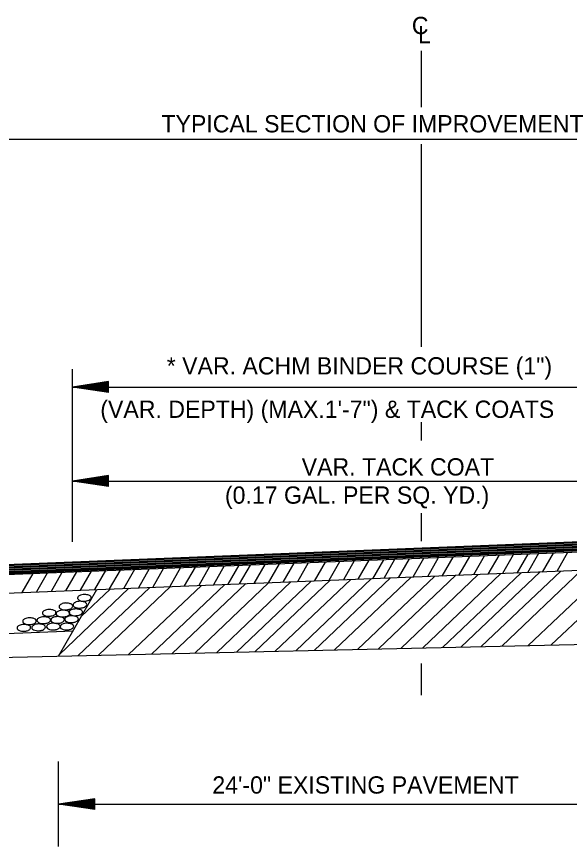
# Model space of a CAD drawing. Extents: x 634177 to 635904, y 289936 to 290970.
# Drawn here: x 635697.85 to 635717.06, y 290601.34 to 290630.14 of the extents above; entities that cross this region are included whole.
import ezdxf

# ---------------------------------------------------------------- set-up
doc = ezdxf.new("R2010")
doc.units = 0
doc.layers.add('R_Draft', color=7, linetype='Continuous')

msp = doc.modelspace()

# ---------------------------------------------------------------- linework, layer by layer
at = {"layer": 'R_Draft'}
for p, q in [((635711.924, 290627.005), (635711.924, 290628.954)), ((635679.883, 290625.883), (635743.99, 290625.883)), ((635711.924, 290619.424), (635711.924, 290625.719)), ((635711.924, 290618.681), (635711.924, 290619.424)), ((635699.794, 290611.916), (635699.794, 290617.9)), ((635701.05, 290617.472), (635699.794, 290617.281)), ((635701.05, 290617.438), (635700.002, 290617.281)), ((635701.05, 290617.41), (635700.218, 290617.281)), ((635701.05, 290617.375), (635700.429, 290617.281)), ((635701.05, 290617.345), (635700.641, 290617.281)), ((635701.05, 290617.311), (635700.853, 290617.281)), ((635701.05, 290617.092), (635701.05, 290617.472)), ((635699.794, 290617.281), (635723.977, 290617.281)), ((635701.05, 290617.092), (635699.794, 290617.281)), ((635701.05, 290617.123), (635700.002, 290617.281)), ((635701.05, 290617.154), (635700.218, 290617.281)), ((635701.05, 290617.187), (635700.429, 290617.281)), ((635701.05, 290617.218), (635700.641, 290617.281)), ((635701.05, 290617.252), (635700.853, 290617.281)), ((635711.924, 290615.433), (635711.924, 290616.064)), ((635701.05, 290614.21), (635699.794, 290614.022)), ((635701.05, 290614.181), (635700.002, 290614.022)), ((635701.05, 290614.147), (635700.218, 290614.022)), ((635701.05, 290613.833), (635701.05, 290614.21)), ((635699.794, 290614.022), (635723.977, 290614.022)), ((635701.05, 290613.833), (635699.794, 290614.022)), ((635701.05, 290613.867), (635700.002, 290614.022)), ((635701.05, 290613.897), (635700.218, 290614.022)), ((635701.05, 290614.118), (635700.429, 290614.022)), ((635701.05, 290613.929), (635700.429, 290614.022)), ((635701.05, 290614.082), (635700.641, 290614.022)), ((635701.05, 290613.961), (635700.641, 290614.022)), ((635701.05, 290614.054), (635700.853, 290614.022)), ((635701.05, 290613.994), (635700.853, 290614.022)), ((635679.556, 290610.253), (635744.281, 290612.835)), ((635679.64, 290610.297), (635744.208, 290612.871)), ((635679.723, 290610.336), (635744.137, 290612.908)), ((635679.808, 290610.381), (635744.062, 290612.944)), ((635679.883, 290610.417), (635743.993, 290612.978)), ((635711.924, 290611.934), (635711.924, 290612.906)), ((635689.335, 290610.448), (635734.489, 290612.244)), ((635689.363, 290610.485), (635734.463, 290612.283)), ((635689.387, 290610.527), (635734.437, 290612.321)), ((635689.411, 290610.565), (635734.412, 290612.357)), ((635689.438, 290610.606), (635734.383, 290612.4)), ((635688.923, 290609.788), (635734.918, 290611.618)), ((635710.09, 290611.27), (635709.713, 290610.611)), ((635710.596, 290611.289), (635710.217, 290610.632)), ((635710.986, 290611.297), (635710.609, 290610.641)), ((635711.493, 290611.315), (635711.114, 290610.662)), ((635711.997, 290611.336), (635711.619, 290610.679)), ((635712.501, 290611.36), (635712.125, 290610.7)), ((635713.008, 290611.378), (635712.632, 290610.722)), ((635713.593, 290611.399), (635713.213, 290610.742)), ((635714.096, 290611.411), (635713.724, 290610.763)), ((635714.604, 290611.442), (635714.229, 290610.784)), ((635715.112, 290611.46), (635714.733, 290610.807)), ((635715.616, 290611.48), (635715.239, 290610.824)), ((635715.988, 290611.5), (635715.609, 290610.84)), ((635716.496, 290611.521), (635716.115, 290610.861)), ((635716.998, 290611.537), (635716.623, 290610.885)), ((635702.459, 290610.974), (635702.083, 290610.316)), ((635702.962, 290610.993), (635702.586, 290610.336)), ((635703.548, 290611.018), (635703.171, 290610.36)), ((635704.052, 290611.029), (635703.679, 290610.381)), ((635704.56, 290611.056), (635704.184, 290610.4)), ((635705.067, 290611.077), (635704.69, 290610.421)), ((635705.57, 290611.099), (635705.194, 290610.443)), ((635705.964, 290611.104), (635705.587, 290610.45)), ((635706.475, 290611.124), (635706.095, 290610.466)), ((635706.976, 290611.144), (635706.599, 290610.488)), ((635707.483, 290611.165), (635707.105, 290610.509)), ((635707.986, 290611.185), (635707.61, 290610.528)), ((635708.57, 290611.208), (635708.192, 290610.549)), ((635709.073, 290611.219), (635708.701, 290610.573)), ((635709.586, 290611.248), (635709.206, 290610.594)), ((635716.432, 290608.33), (635719.244, 290610.994)), ((635698.415, 290610.809), (635698.036, 290610.15)), ((635698.915, 290610.818), (635698.543, 290610.171)), ((635699.425, 290610.845), (635699.048, 290610.19)), ((635699.933, 290610.868), (635699.554, 290610.212)), ((635700.438, 290610.888), (635700.06, 290610.233)), ((635700.942, 290610.912), (635700.563, 290610.255)), ((635701.449, 290610.932), (635701.073, 290610.276)), ((635701.953, 290610.956), (635701.576, 290610.298)), ((635708.901, 290608.16), (635711.568, 290610.687)), ((635709.698, 290608.178), (635712.388, 290610.723)), ((635710.424, 290608.193), (635713.119, 290610.752)), ((635711.202, 290608.212), (635713.896, 290610.781)), ((635711.966, 290608.229), (635714.681, 290610.815)), ((635712.655, 290608.246), (635715.385, 290610.84)), ((635713.291, 290608.258), (635716.043, 290610.868)), ((635713.997, 290608.274), (635716.76, 290610.896)), ((635714.716, 290608.291), (635717.486, 290610.924)), ((635715.633, 290608.314), (635718.424, 290610.965)), ((635701.743, 290608), (635704.271, 290610.397)), ((635702.541, 290608.016), (635705.092, 290610.432)), ((635703.263, 290608.032), (635705.823, 290610.459)), ((635704.042, 290608.05), (635706.603, 290610.491)), ((635704.805, 290608.069), (635707.384, 290610.526)), ((635705.494, 290608.083), (635708.09, 290610.549)), ((635706.133, 290608.097), (635708.748, 290610.578)), ((635706.839, 290608.113), (635709.464, 290610.605)), ((635707.559, 290608.131), (635710.19, 290610.635)), ((635708.19, 290608.144), (635710.847, 290610.662)), ((635699.307, 290607.945), (635700.637, 290610.254)), ((635699.334, 290607.992), (635701.757, 290610.301)), ((635699.98, 290607.957), (635702.477, 290610.325)), ((635700.097, 290609.317), (635701.1, 290610.272)), ((635700.703, 290607.975), (635703.203, 290610.356)), ((635674.699, 290607.826), (635699.814, 290608.826)), ((635694.262, 290607.831), (635729.503, 290608.624)), ((635711.924, 290606.59), (635711.924, 290607.688)), ((635699.307, 290601.338), (635699.307, 290604.281)), ((635700.565, 290602.994), (635699.307, 290602.804)), ((635700.565, 290602.964), (635699.516, 290602.804)), ((635700.565, 290602.929), (635699.735, 290602.804)), ((635700.565, 290602.617), (635700.565, 290602.994)), ((635699.307, 290602.804), (635724.472, 290602.804)), ((635700.565, 290602.617), (635699.307, 290602.804)), ((635700.565, 290602.649), (635699.516, 290602.804)), ((635700.565, 290602.68), (635699.735, 290602.804)), ((635700.565, 290602.902), (635699.942, 290602.804)), ((635700.565, 290602.711), (635699.942, 290602.804)), ((635700.565, 290602.865), (635700.157, 290602.804)), ((635700.565, 290602.743), (635700.157, 290602.804)), ((635700.565, 290602.838), (635700.366, 290602.804)), ((635700.565, 290602.776), (635700.366, 290602.804))]:
    msp.add_line(p, q, dxfattribs=at)
for points in [[(635700.051, 290609.614), (635699.967, 290609.615), (635699.875, 290609.648), (635699.822, 290609.693), (635699.816, 290609.719), (635699.838, 290609.775), (635699.87, 290609.798), (635699.923, 290609.825), (635700.005, 290609.843), (635700.044, 290609.847), (635700.108, 290609.842), (635700.176, 290609.831), (635700.23, 290609.813), (635700.28, 290609.77), (635700.289, 290609.741), (635700.274, 290609.695), (635700.236, 290609.661), (635700.198, 290609.637), (635700.141, 290609.623), (635700.104, 290609.615), (635700.051, 290609.614)], [(635700.205, 290609.853), (635700.121, 290609.855), (635700.029, 290609.887), (635699.976, 290609.932), (635699.97, 290609.958), (635699.992, 290610.014), (635700.024, 290610.038), (635700.077, 290610.064), (635700.159, 290610.083), (635700.198, 290610.087), (635700.262, 290610.081), (635700.33, 290610.071), (635700.384, 290610.052), (635700.434, 290610.009), (635700.443, 290609.981), (635700.428, 290609.934), (635700.39, 290609.9), (635700.352, 290609.877), (635700.295, 290609.863), (635700.258, 290609.855), (635700.205, 290609.853)], [(635698.982, 290609.331), (635698.898, 290609.333), (635698.806, 290609.365), (635698.753, 290609.411), (635698.747, 290609.437), (635698.769, 290609.492), (635698.801, 290609.516), (635698.854, 290609.543), (635698.936, 290609.561), (635698.975, 290609.565), (635699.039, 290609.56), (635699.107, 290609.549), (635699.161, 290609.53), (635699.211, 290609.488), (635699.22, 290609.459), (635699.205, 290609.412), (635699.167, 290609.378), (635699.129, 290609.355), (635699.072, 290609.341), (635699.035, 290609.333), (635698.982, 290609.331)], [(635699.461, 290609.306), (635699.377, 290609.307), (635699.285, 290609.34), (635699.232, 290609.385), (635699.226, 290609.411), (635699.248, 290609.467), (635699.28, 290609.49), (635699.333, 290609.517), (635699.415, 290609.536), (635699.454, 290609.54), (635699.517, 290609.534), (635699.586, 290609.523), (635699.64, 290609.505), (635699.69, 290609.462), (635699.699, 290609.434), (635699.684, 290609.387), (635699.646, 290609.353), (635699.608, 290609.329), (635699.551, 290609.315), (635699.514, 290609.307), (635699.461, 290609.306)], [(635699.563, 290609.554), (635699.479, 290609.555), (635699.388, 290609.588), (635699.335, 290609.633), (635699.329, 290609.659), (635699.351, 290609.715), (635699.382, 290609.738), (635699.436, 290609.765), (635699.517, 290609.784), (635699.556, 290609.788), (635699.62, 290609.782), (635699.689, 290609.771), (635699.742, 290609.753), (635699.792, 290609.71), (635699.801, 290609.682), (635699.787, 290609.635), (635699.749, 290609.601), (635699.711, 290609.577), (635699.653, 290609.564), (635699.617, 290609.555), (635699.563, 290609.554)], [(635699.906, 290609.349), (635699.821, 290609.35), (635699.73, 290609.383), (635699.677, 290609.428), (635699.671, 290609.454), (635699.693, 290609.51), (635699.724, 290609.533), (635699.778, 290609.56), (635699.86, 290609.578), (635699.898, 290609.582), (635699.962, 290609.577), (635700.031, 290609.566), (635700.084, 290609.548), (635700.135, 290609.505), (635700.143, 290609.476), (635700.129, 290609.429), (635700.091, 290609.395), (635700.053, 290609.372), (635699.995, 290609.358), (635699.959, 290609.35), (635699.906, 290609.349)], [(635698.298, 290609.041), (635698.214, 290609.042), (635698.122, 290609.075), (635698.069, 290609.12), (635698.063, 290609.146), (635698.085, 290609.202), (635698.117, 290609.225), (635698.17, 290609.252), (635698.252, 290609.27), (635698.29, 290609.274), (635698.354, 290609.269), (635698.423, 290609.258), (635698.476, 290609.24), (635698.527, 290609.197), (635698.535, 290609.168), (635698.521, 290609.122), (635698.483, 290609.088), (635698.445, 290609.064), (635698.387, 290609.05), (635698.351, 290609.042), (635698.298, 290609.041)], [(635698.794, 290609.075), (635698.71, 290609.076), (635698.618, 290609.109), (635698.565, 290609.154), (635698.559, 290609.18), (635698.581, 290609.236), (635698.613, 290609.259), (635698.666, 290609.286), (635698.748, 290609.305), (635698.786, 290609.309), (635698.85, 290609.303), (635698.919, 290609.292), (635698.973, 290609.274), (635699.023, 290609.231), (635699.032, 290609.203), (635699.017, 290609.156), (635698.979, 290609.122), (635698.941, 290609.098), (635698.884, 290609.085), (635698.847, 290609.076), (635698.794, 290609.075)], [(635699.273, 290609.083), (635699.189, 290609.085), (635699.097, 290609.117), (635699.044, 290609.163), (635699.038, 290609.189), (635699.06, 290609.244), (635699.092, 290609.268), (635699.145, 290609.295), (635699.227, 290609.313), (635699.265, 290609.317), (635699.329, 290609.312), (635699.398, 290609.301), (635699.451, 290609.282), (635699.502, 290609.24), (635699.511, 290609.211), (635699.496, 290609.164), (635699.458, 290609.13), (635699.42, 290609.107), (635699.362, 290609.093), (635699.326, 290609.085), (635699.273, 290609.083)], [(635699.76, 290609.109), (635699.676, 290609.111), (635699.585, 290609.143), (635699.531, 290609.188), (635699.526, 290609.214), (635699.547, 290609.27), (635699.579, 290609.293), (635699.632, 290609.32), (635699.714, 290609.339), (635699.753, 290609.343), (635699.817, 290609.337), (635699.886, 290609.327), (635699.939, 290609.308), (635699.989, 290609.265), (635699.998, 290609.237), (635699.983, 290609.19), (635699.945, 290609.156), (635699.907, 290609.133), (635699.85, 290609.119), (635699.814, 290609.111), (635699.76, 290609.109)], [(635698.101, 290608.81), (635698.017, 290608.811), (635697.925, 290608.844), (635697.872, 290608.889), (635697.866, 290608.915), (635697.888, 290608.971), (635697.92, 290608.994), (635697.973, 290609.021), (635698.055, 290609.039), (635698.094, 290609.043), (635698.158, 290609.038), (635698.226, 290609.027), (635698.28, 290609.009), (635698.33, 290608.966), (635698.339, 290608.938), (635698.324, 290608.891), (635698.286, 290608.857), (635698.248, 290608.833), (635698.191, 290608.819), (635698.154, 290608.811), (635698.101, 290608.81)], [(635698.614, 290608.827), (635698.53, 290608.828), (635698.439, 290608.861), (635698.385, 290608.906), (635698.38, 290608.932), (635698.401, 290608.988), (635698.433, 290609.011), (635698.486, 290609.038), (635698.568, 290609.057), (635698.607, 290609.061), (635698.671, 290609.055), (635698.74, 290609.044), (635698.793, 290609.026), (635698.843, 290608.983), (635698.852, 290608.955), (635698.837, 290608.908), (635698.799, 290608.874), (635698.761, 290608.85), (635698.704, 290608.837), (635698.668, 290608.828), (635698.614, 290608.827)], [(635699.127, 290608.852), (635699.043, 290608.854), (635698.952, 290608.886), (635698.898, 290608.932), (635698.893, 290608.958), (635698.915, 290609.013), (635698.946, 290609.037), (635699, 290609.064), (635699.081, 290609.082), (635699.12, 290609.086), (635699.184, 290609.081), (635699.253, 290609.07), (635699.306, 290609.051), (635699.356, 290609.009), (635699.365, 290608.98), (635699.351, 290608.933), (635699.313, 290608.899), (635699.275, 290608.876), (635699.217, 290608.862), (635699.181, 290608.854), (635699.127, 290608.852)], [(635699.598, 290608.852), (635699.514, 290608.854), (635699.422, 290608.886), (635699.369, 290608.932), (635699.363, 290608.958), (635699.385, 290609.013), (635699.417, 290609.037), (635699.47, 290609.064), (635699.552, 290609.082), (635699.59, 290609.086), (635699.654, 290609.081), (635699.723, 290609.07), (635699.776, 290609.051), (635699.827, 290609.009), (635699.836, 290608.98), (635699.821, 290608.933), (635699.783, 290608.899), (635699.745, 290608.876), (635699.687, 290608.862), (635699.651, 290608.854), (635699.598, 290608.852)]]:
    msp.add_spline(points, degree=3, dxfattribs=at)

# ---------------------------------------------------------------- texts
for s, p in [('C', (635711.586, 290629.535)), ('L', (635711.801, 290629.218)), ('TYPICAL SECTION OF IMPROVEMENT', (635702.885, 290626.123)), ('* VAR. ACHM BINDER COURSE (1")', (635703.069, 290617.72)), ('(VAR. DEPTH) (MAX.1\'-7") & TACK COATS', (635700.76, 290616.214)), ('VAR. TACK COAT', (635707.759, 290614.213)), ('(0.17 GAL. PER SQ. YD.)', (635705.091, 290613.234)), ('24\'-0" EXISTING PAVEMENT', (635704.653, 290603.171))]:
    msp.add_text(s, height=0.6, dxfattribs=at).set_placement(p)

doc.saveas('drawing.dxf')
